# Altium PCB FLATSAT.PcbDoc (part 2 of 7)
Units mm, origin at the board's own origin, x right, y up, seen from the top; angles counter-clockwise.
Board outline 430 x 350 mm, 5 copper layers (Top Layer, Internal Plane 1, Internal Plane 2, DELETEME, Bottom Layer); 808 components, 852 nets, 6407 pads, 939 vias.
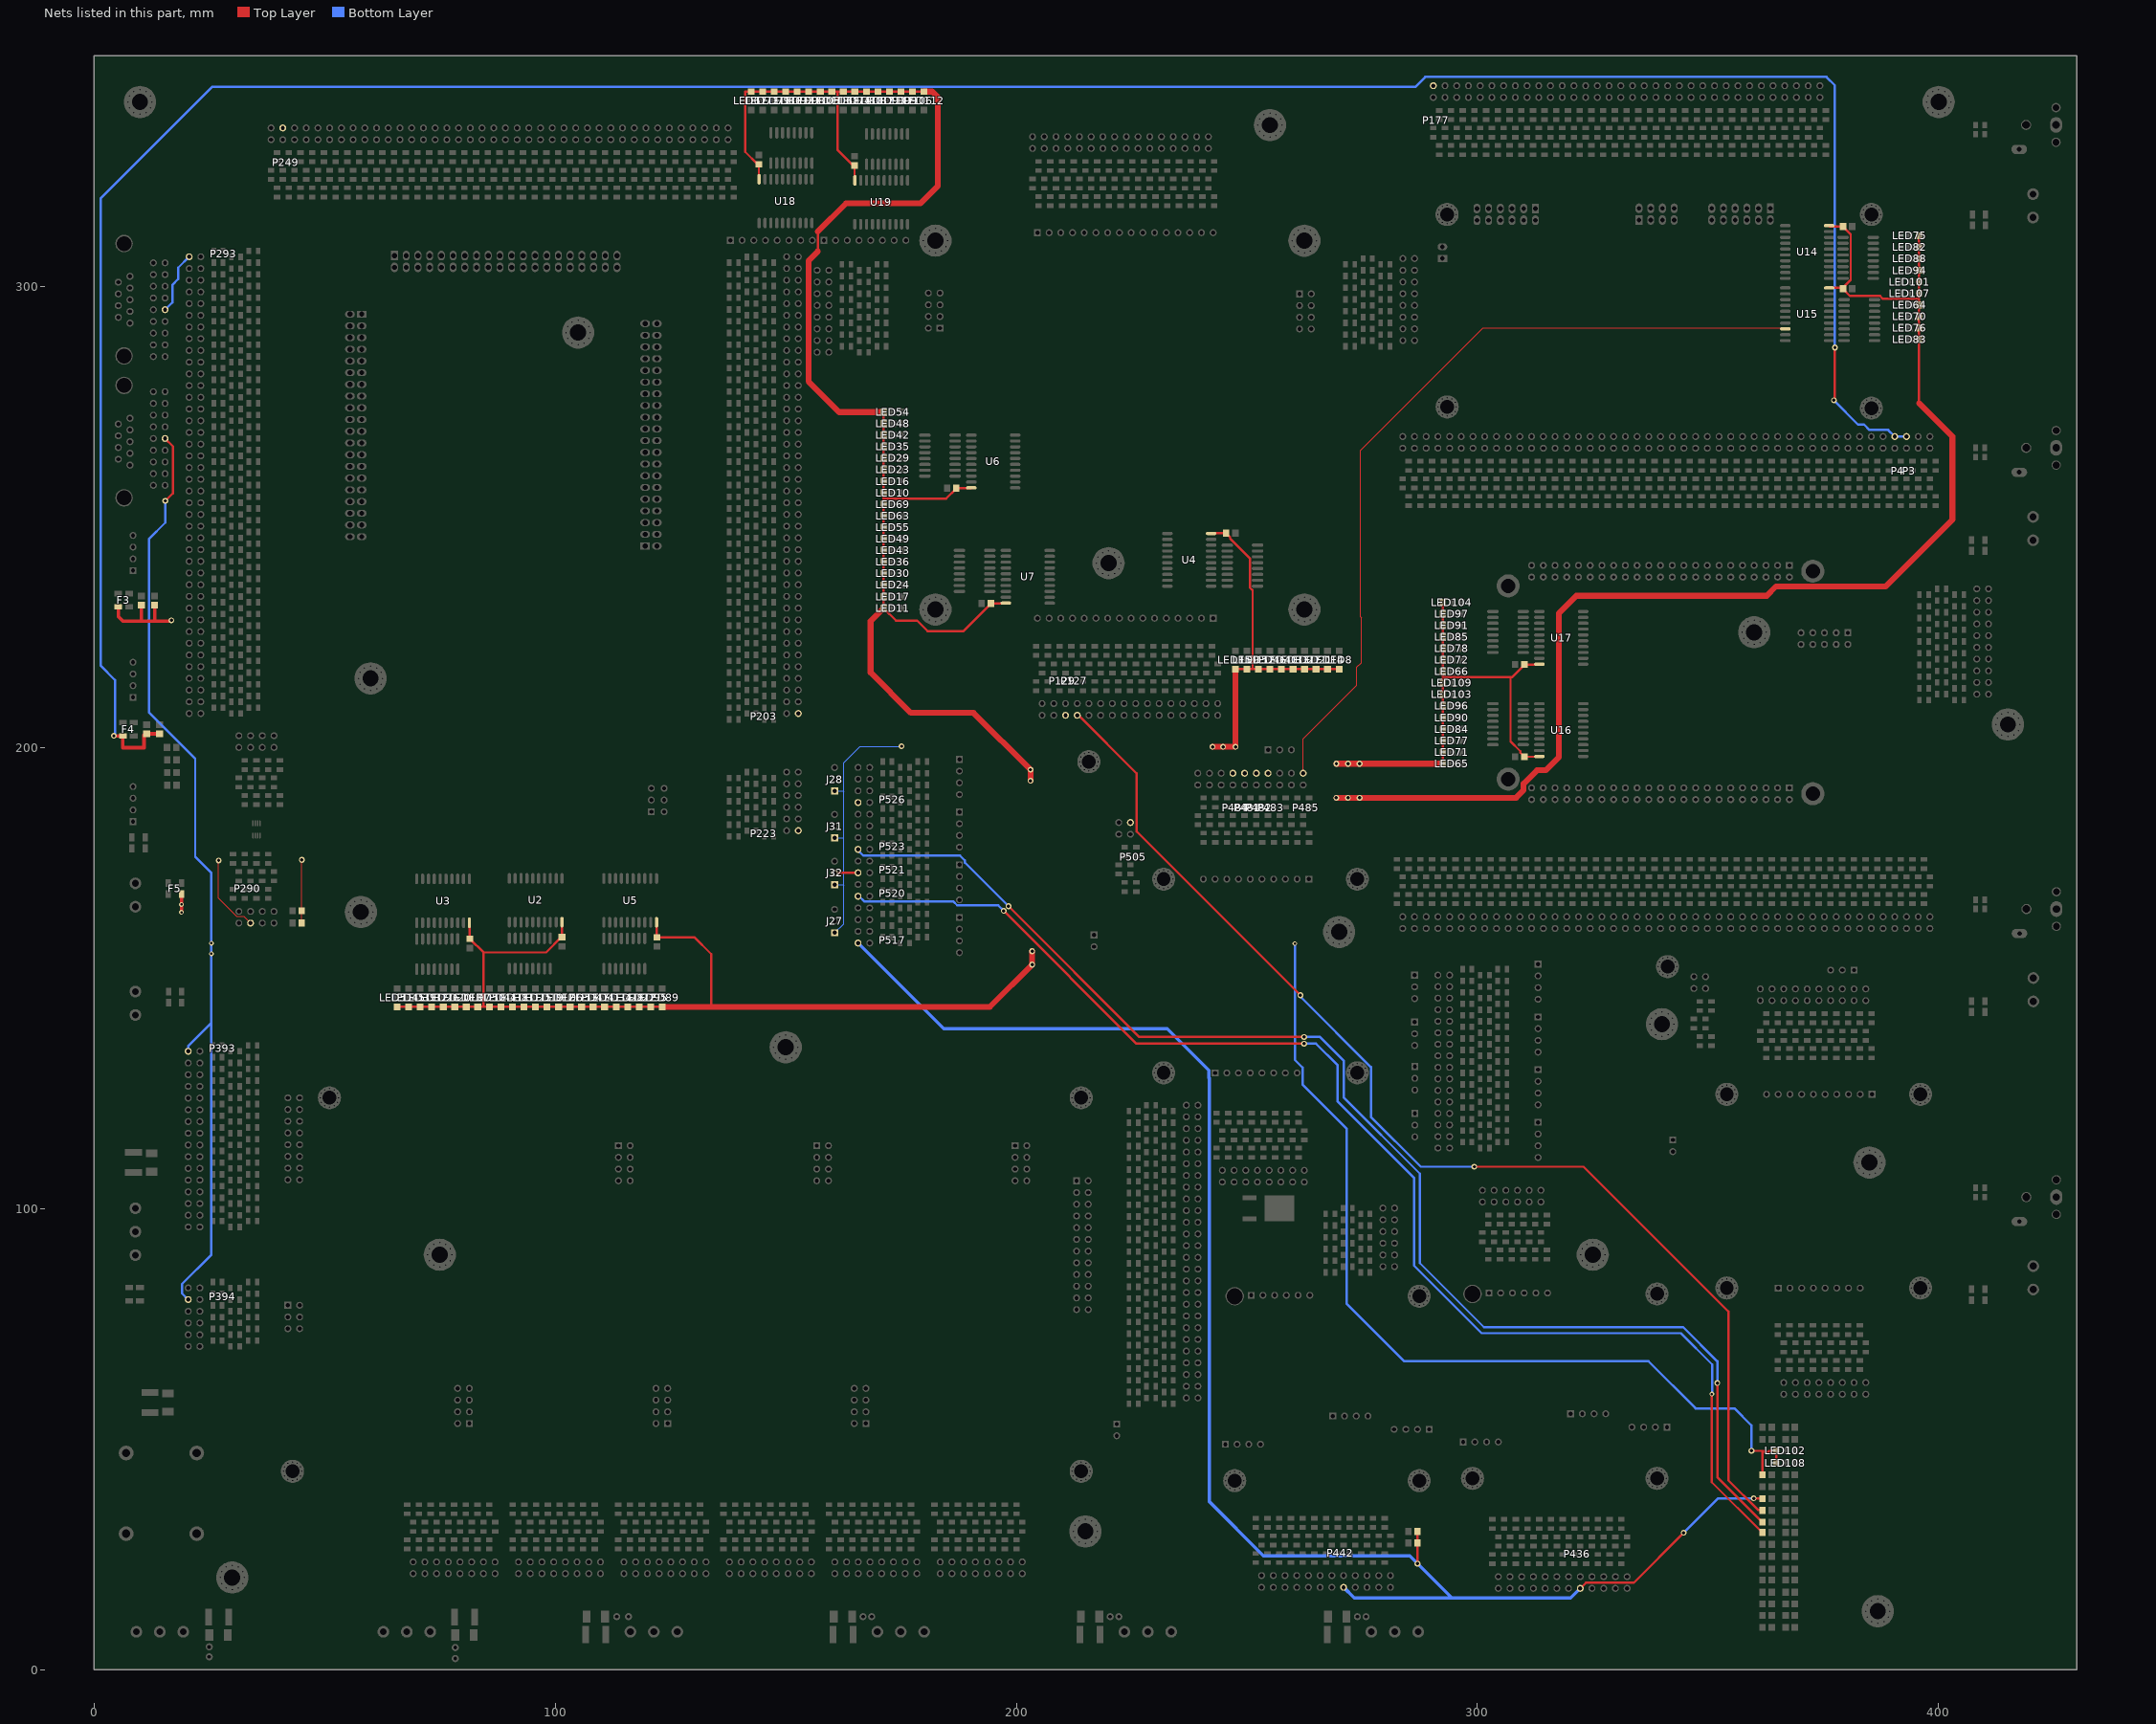
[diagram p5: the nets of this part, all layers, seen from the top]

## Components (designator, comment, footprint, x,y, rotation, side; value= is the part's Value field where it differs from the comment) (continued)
P532 "Jumper_Filter" Jumper_filter#1 291.418,123.14 r0 top
P533 "Jumper_Filter" Jumper_filter#1 291.418,128.14 r0 top
P534 "Jumper_Filter" Jumper_filter#1 291.418,130.64 r0 top
P535 "Jumper_Filter" Jumper_filter#1 291.418,133.14 r0 top
P536 "Jumper_Filter" Jumper_filter#1 291.418,138.14 r0 top
P537 "Jumper_Filter" Jumper_filter#1 291.418,140.64 r0 top
P538 "Jumper_Filter" Jumper_filter#1 291.418,143.14 r0 top
P539 "Jumper_Filter" Jumper_filter#1 291.418,148.14 r0 top
P540 "Jumper_Filter" Jumper_filter#1 291.418,150.64 r0 top
R1 "1206 Resistor" 6-0805_M 14.224,203.962 r90 top
R2 "1206 Resistor" 6-0805_M 11.43,203.962 r90 top
R3 "1206 Resistor" 6-0805_M 13.183,231.877 r90 top
R4 "1206 Resistor" 6-0805_M 10.312,231.877 r90 top
R5 "1206 Resistor" 6-0805_M 286,27.5 r180 top
R6 "1206 Resistor" 6-0805_M 286,30 r180 top
R7 "1206 Resistor" 6-0805_M 44.069,164.592 r180 top
R8 "1206 Resistor" 6-0805_M 44.069,161.925 r180 top
R9 "1206 Resistor" 6-0805_M 16.904,191.829 r0 top
R10 "1206 Resistor" 6-0805_M 16.904,194.579 r0 top
R11 "1206 Resistor" 6-0805_M 16.904,197.329 r0 top
R12 "Res2" 6-0805_M 362.803,52.585 r180 top
R13 "Res2" 6-0805_M 362.803,49.965 r180 top
R14 "Res2" 6-0805_M 362.803,42.265 r180 top
R15 "Res2" 6-0805_M 362.803,39.685 r180 top
R16 "Res2" 6-0805_M 362.803,37.105 r180 top
R17 "Res2" 6-0805_M 362.803,34.525 r180 top
R18 "Res2" 6-0805_M 362.803,32.025 r180 top
R19 "Res2" 6-0805_M 362.803,29.765 r180 top
R20 "Res2" 6-0805_M 362.803,27.185 r180 top
R21 "Res2" 6-0805_M 362.803,24.605 r180 top
R22 "Res2" 6-0805_M 362.803,21.865 r180 top
R23 "Res2" 6-0805_M 362.803,19.445 r180 top
R24 "Res2" 6-0805_M 362.803,11.785 r180 top
R25 "Res2" 6-0805_M 362.803,16.825 r180 top
R26 "Res2" 6-0805_M 362.803,9.165 r180 top
R27 "Res2" 6-0805_M 362.803,14.245 r180 top
SW1 "3V3" LVSwitcher 277.956,125.459 r90 top locked
SW2 "5V0" LVSwitcher 400.059,78.786 r90 top locked
TRX1 "TRX_REGULATOR" TRX_REGULATOR 342.218,84.66 r180 top locked
TRX2 "TRX_REGULATOR" TRX_REGULATOR 290.656,84.168 r180 top locked
U1 "PCA9306" TSSOP50P310X90-8N 35.249,182.24 r90 top
U2 "MC74VHC541DW" 751D-04_M 95.79,166.875 r270 top
U3 "MC74VHC541DW" 751D-04_M 75.715,166.75 r270 top
U4 "MC74VHC541DW" 751D-04_M 237.5,240.715 r0 top
U5 "MC74VHC541DW" 751D-04_M 116.288,166.85 r270 top
U6 "MC74VHC541DW" 751D-04_M 195,262.035 r180 top
U7 "MC74VHC541DW" 751D-04_M 202.5,237.035 r180 top
U8 "SOMC1603" SOMC1603 89.059,160.366 r270 top
U9 "SOMC1603" SOMC1603 68.984,160.241 r270 top
U10 "SOMC1603" SOMC1603 244.009,233.984 r0 top
U11 "SOMC1603" SOMC1603 109.557,160.341 r270 top
U12 "SOMC1603" SOMC1603 188.491,268.766 r180 top
U13 "SOMC1603" SOMC1603 195.991,243.766 r180 top
U14 "MC74VHC541DW" 751D-04_M 371.5,307.465 r0 top
U15 "MC74VHC541DW" 751D-04_M 371.5,293.965 r0 top
U16 "MC74VHC541DW" 751D-04_M 318.171,203.785 r180 top
U17 "MC74VHC541DW" 751D-04_M 318.171,223.785 r180 top
U18 "MC74VHC541DW" 751D-04_M 149.965,318.5 r90 top
U19 "MC74VHC541DW" 751D-04_M 170.715,318.25 r90 top
U20 "SOMC1603" SOMC1603 377.509,300.734 r0 top
U21 "SOMC1603" SOMC1603 377.759,287.234 r0 top
U22 "SOMC1603" SOMC1603 311.662,210.516 r180 top
U23 "SOMC1603" SOMC1603 311.662,230.516 r180 top
U24 "SOMC1603" SOMC1603 156.696,325.009 r90 top
U25 "SOMC1603" SOMC1603 177.446,324.759 r90 top

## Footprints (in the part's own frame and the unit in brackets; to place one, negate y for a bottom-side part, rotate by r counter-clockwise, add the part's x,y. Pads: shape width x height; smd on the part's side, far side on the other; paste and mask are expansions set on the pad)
4MM_BANANA [mm] "DELTRON 571-0x00"
  round 3.2 hole 1.8: 1(0,0) 1(15.3,0)
  silkscreen extent -2.5,-5 20.25,5
6-0805_M [mm] "Chip Resistor, Body 2.0x1.2mm, IPC Low Density"
  rect 1.4x1.5 smd: 1(-1,0) 2(1,0)
  silkscreen extent 0,-0.65 0,0.65, body extent -1.07,-0.7 1.07,0.7, height 0.7
751D-04_M [mm] "SOIC, 20-Leads, Body 12.8x7.5mm, Pitch 1.27mm, IPC Low Density"
  oval 2.3x0.7 smd: 1(-4.75,5.715) 2(-4.75,4.445) 3(-4.75,3.175) 4(-4.75,1.905) 5(-4.75,0.635) 6(-4.75,-0.635) 7(-4.75,-1.905) 8(-4.75,-3.175) 9(-4.75,-4.445) 10(-4.75,-5.715) 11(4.75,-5.715) 12(4.75,-4.445) 13(4.75,-3.175) 14(4.75,-1.905) 15(4.75,-0.635) 16(4.75,0.635) 17(4.75,1.905) 18(4.75,3.175) 19(4.75,4.445) 20(4.75,5.715)
  silkscreen extent -4.87,-6.5 3.2,6.74, body extent -3.8,-6.5 3.8,6.5, height 2.65
BCR [mm]
  round 1 hole 0.3: 0(2.5,85.5) 0(2.5,4.5) 0(2.768,84.5) 0(2.768,86.5) 0(2.768,5.5) 0(2.768,3.5) 0(3.5,87.232) 0(3.5,83.768) 0(3.5,6.232) 0(3.5,2.768) 0(4.5,87.5) 0(4.5,83.5) 0(4.5,6.5) 0(4.5,2.5) 0(5.5,87.232) 0(5.5,83.768) 0(5.5,6.232) 0(5.5,2.768) 0(6.232,86.5) 0(6.232,84.5) 0(6.232,3.5) 0(6.232,5.5) 0(6.5,85.5) 0(6.5,4.5) 0(165.5,4.5) 0(165.768,3.5) 0(165.768,5.5) 0(166.5,2.768) 0(166.5,6.232) 0(167.5,2.5) 0(167.5,6.5) 0(168.5,2.768) 0(168.5,6.232) 0(169.232,3.5) 0(169.232,5.5) 0(169.5,4.5) 0(173.5,85.5) 0(173.768,84.5) 0(173.768,86.5) 0(174.5,83.768) 0(174.5,87.232) 0(175.5,83.5) 0(175.5,87.5) 0(176.5,83.768) 0(176.5,87.232) 0(177.232,84.5) 0(177.232,86.5) 0(177.5,85.5)
  round 5 hole 3: 0(4.5,85.5) 0(4.5,4.5) 0(167.5,4.5) 0(175.5,85.5)
  round 1.5 hole 0.9: 1(173.96,49.5) 1(176.5,4.5) 2(173.96,4.5) 3(173.96,54.58) 3(173.96,7.04) 3(173.96,9.58) 3(173.96,12.12) 3(173.96,14.66) 3(173.96,17.2) 3(173.96,19.74) 3(173.96,22.28) 4(176.5,54.58) 4(176.5,22.28) 5(176.5,14.66) 6(176.5,12.12) 7(176.5,9.58) 8(176.5,7.04) 9(176.5,17.2) 10(176.5,19.74) 11(5.5,50.44) 11(5.5,45.36) 11(5.5,47.9) 11(5.5,40.28) 11(5.5,42.82) 11(5.5,35.2) 11(5.5,37.74) 13(5.5,32.66) 13(5.5,27.58) 13(5.5,30.12) 13(5.5,25.04) 14(-3.2,77.79) 14(2.96,50.44) 14(2.96,47.9) 14(2.96,42.82) 14(2.96,45.36) 14(2.96,40.28) 14(2.96,37.74) 14(2.96,35.2) 14(2.96,32.66) 14(2.96,30.12) 14(2.96,27.58) 14(2.96,22.5) 14(2.96,25.04) 15(61.834,17.407) 15(61.834,19.947) 15(61.834,22.487) 16(59.294,17.407) 16(59.294,19.947) 16(59.294,22.487) 17(59.294,14.867) 18(104.834,17.407) 18(104.834,19.947) 18(104.834,22.487) 19(102.294,17.407) 19(102.294,19.947) 19(102.294,22.487) 20(102.294,14.867) 21(18.834,17.407) 21(18.834,19.947) 21(18.834,22.487) 22(16.294,17.407) 22(16.294,19.947) 22(16.294,22.487) 23(16.294,14.867) 24(94.166,67.513) 24(94.166,70.053) 24(94.166,72.593) 25(96.706,67.513) 25(96.706,70.053) 25(96.706,72.593) 26(96.706,75.133) 27(51.166,72.593) 27(51.166,67.513) 27(51.166,70.053) 28(53.706,67.513) 28(53.706,70.053) 28(53.706,72.593) 29(53.706,75.133) 30(137.166,67.513) 30(137.166,70.053) 30(137.166,72.593) 31(139.706,67.513) 31(139.706,70.053) 31(139.706,72.593) 32(139.706,75.133) 34(176.5,52.04) 35(173.96,52.04)
  rect 1.5x1.5 hole 0.9: 12(-3.2,75.25) 13(5.5,22.5) 15(61.834,14.867) 18(104.834,14.867) 21(18.834,14.867) 24(94.166,75.133) 27(51.166,75.133) 30(137.166,75.133) 33(176.5,49.5)
  silkscreen extent -4.47,0 180,90
Beaglebone [mil]
  rect 60x60 hole 31.5 mask+2.76: A01(2625,-75) B01(2625,-1975) P01(3125,-650)
  round 60 hole 31.5 mask+2.76: A02(2625,-175) A03(2525,-75) A04(2525,-175) A05(2425,-75) A06(2425,-175) A07(2325,-75) A08(2325,-175) A09(2225,-75) A10(2225,-175) A11(2125,-75) A12(2125,-175) A13(2025,-75) A14(2025,-175) A15(1925,-75) A16(1925,-175) A17(1825,-75) A18(1825,-175) A19(1725,-75) A20(1725,-175) A21(1625,-75) A22(1625,-175) A23(1525,-75) A24(1525,-175) A25(1425,-75) A26(1425,-175) A27(1325,-75) A28(1325,-175) A29(1225,-75) A30(1225,-175) A31(1125,-75) A32(1125,-175) A33(1025,-75) A34(1025,-175) A35(925,-75) A36(925,-175) A37(825,-75) A38(825,-175) A39(725,-75) A40(725,-175) A41(625,-75) A42(625,-175) A43(525,-75) A44(525,-175) A45(425,-75) A46(425,-175) B02(2625,-2075) B03(2525,-1975) B04(2525,-2075) B05(2425,-1975) B06(2425,-2075) B07(2325,-1975) B08(2325,-2075) B09(2225,-1975) B10(2225,-2075) B11(2125,-1975) B12(2125,-2075) B13(2025,-1975) B14(2025,-2075) B15(1925,-1975) B16(1925,-2075) B17(1825,-1975) B18(1825,-2075) B19(1725,-1975) B20(1725,-2075) B21(1625,-1975) B22(1625,-2075) B23(1525,-1975) B24(1525,-2075) B25(1425,-1975) B26(1425,-2075) B27(1325,-1975) B28(1325,-2075) B29(1225,-1975) B30(1225,-2075) B31(1125,-1975) B32(1125,-2075) B33(1025,-1975) B34(1025,-2075) B35(925,-1975) B36(925,-2075) B37(825,-1975) B38(825,-2075) B39(725,-1975) B40(725,-2075) B41(625,-1975) B42(625,-2075) B43(525,-1975) B44(525,-2075) B45(425,-1975) B46(425,-2075) P02(3125,-750) P03(3025,-650) P04(3025,-750) P05(2925,-650) P06(2925,-750) P07(2825,-650) P08(2825,-750) P09(2725,-650) P10(2725,-750)
  round 196.85 hole 122.05 mask+2.76: M1(225,-250) M2(225,-1900) M3(2825,-125) M4(2825,-2025)
  silkscreen extent 0,-2150 3400,0
"BIDIRECTIONAL LED" [mm]
  rect 1.4x1.5 smd: 1(-1,0) 2(1,0) 3(3,0)
  silkscreen extent -2.02,1.15 -2,1.15
Communications [mm] "Communications"
  round 1.5 hole 0.9: AFSK1_M0(32.192,86.733) AFSK1_M1(29.652,86.733) AFSK1_RXD(34.732,86.733) AFSK2_M0(62.672,86.733) AFSK2_M1(60.132,86.733) AFSK2_RXD(65.212,86.733) AFSK2_TXD(57.592,86.733) DTMF1_Q1(52.512,3.113) DTMF1_Q2(55.052,3.113) DTMF1_Q3(57.592,3.113) DTMF1_Q4(60.132,3.113) DTMF1_ST(62.672,3.113) DTMF2_ES(49.972,3.113) DTMF2_Q1(37.272,3.113) DTMF2_Q2(39.812,3.113) DTMF2_Q3(42.352,3.113) DTMF2_Q4(44.892,3.113) DTMF2_ST(47.432,3.113) GMSK_RX1(83.952,70.923) GMSK_RX2(83.952,65.843) GMSK_TX2(83.952,68.383) GND(3.462,66.013) GND(3.462,68.553) GND(3.462,71.093) GND(3.462,73.633) GND(27.112,3.113) GND(29.652,3.113) GND(86.492,65.843) GND(86.492,68.383) GND(86.492,70.923) GND(86.492,73.463) RX1(6.002,68.553) S0(55.052,86.733) S1(52.512,86.733) S2(49.972,86.733) S3(47.432,86.733) S4(44.892,86.733) S5(42.352,86.733) S6(39.812,86.733) S7(37.272,86.733) TX1(6.002,73.633) TX2(6.002,71.093) VCC(32.192,3.113) VCC(34.732,3.113)
  rect 1.5x1.5 hole 0.9: AFSK1_TXD(27.112,86.733) DTMF1_ES(65.212,3.113) GMSK_TX1(83.952,73.463) RX2(6.002,66.013)
  round 1 hole 0.3: ""(2.377,5.013) ""(2.377,85.013) ""(2.729,3.701) ""(2.729,6.325) ""(2.729,83.701) ""(2.729,86.325) ""(3.69,7.286) ""(3.69,87.286) ""(3.69,2.74) ""(3.69,82.74) ""(5.002,2.388) ""(5.002,7.638) ""(5.002,82.388) ""(5.002,87.638) ""(6.314,2.74) ""(6.314,7.286) ""(6.314,82.74) ""(6.314,87.286) ""(7.275,3.701) ""(7.275,83.701) ""(7.275,6.325) ""(7.275,86.325) ""(7.627,5.013) ""(7.627,85.013) ""(82.375,85) ""(82.377,5.013) ""(82.727,83.688) ""(82.727,86.312) ""(82.729,3.701) ""(82.729,6.325) ""(83.688,87.273) ""(83.688,82.727) ""(83.69,7.286) ""(83.69,2.74) ""(85,82.375) ""(85,87.625) ""(85.002,2.388) ""(85.002,7.638) ""(86.312,82.727) ""(86.312,87.273) ""(86.314,2.74) ""(86.314,7.286) ""(87.273,83.688) ""(87.273,86.312) ""(87.275,3.701) ""(87.275,6.325) ""(87.625,85) ""(87.627,5.013)
  round 7 hole 3.5: ""(5.002,5.013) ""(5.002,85.013) ""(85,85) ""(85.002,5.013)
  silkscreen extent 0,0.01 90,90.01
CSC [mm] "Critical Systems Computer"
  rect 1.5x2.1 hole 1.1: C1_1(68.259,68.588) C3_1(17.967,7.12)
  oval 1.5x2.1 hole 1.1: C1_2(68.259,71.128) C1_3(65.719,68.588) C1_4(65.719,71.128) C1_5(63.179,68.588) C1_6(63.179,71.128) C1_7(60.639,68.588) C1_8(60.639,71.128) C1_9(58.099,68.588) C1_10(58.099,71.128) C1_11(55.559,68.588) C1_12(55.559,71.128) C1_13(53.019,68.588) C1_14(53.019,71.128) C1_15(50.479,68.588) C1_16(50.479,71.128) C1_17(47.939,68.588) C1_18(47.939,71.128) C1_19(45.399,68.588) C1_20(45.399,71.128) C1_21(42.859,68.588) C1_22(42.859,71.128) C1_23(40.319,68.588) C1_24(40.319,71.128) C1_25(37.779,68.588) C1_26(37.779,71.128) C1_27(35.239,68.588) C1_28(35.239,71.128) C1_29(32.699,68.588) C1_30(32.699,71.128) C1_31(30.159,68.588) C1_32(30.159,71.128) C1_33(27.619,68.588) C1_34(27.619,71.128) C1_35(25.079,68.588) C1_36(25.079,71.128) C1_37(22.539,68.588) C1_38(22.539,71.128) C1_39(19.999,68.588) C1_40(19.999,71.128) C3_2(17.967,4.58) C3_3(20.507,7.12) C3_4(20.507,4.58) C3_5(23.047,7.12) C3_6(23.047,4.58) C3_7(25.587,7.12) C3_8(25.587,4.58) C3_9(28.127,7.12) C3_10(28.127,4.58) C3_11(30.667,7.12) C3_12(30.667,4.58) C3_13(33.207,7.12) C3_14(33.207,4.58) C3_15(35.747,7.12) C3_16(35.747,4.58) C3_17(38.287,7.12) C3_18(38.287,4.58) C3_19(40.827,7.12) C3_20(40.827,4.58) C3_21(43.367,7.12) C3_22(43.367,4.58) C3_23(45.907,7.12) C3_24(45.907,4.58) C3_25(48.447,7.12) C3_26(48.447,4.58) C3_27(50.987,7.12) C3_28(50.987,4.58) C3_29(53.527,7.12) C3_30(53.527,4.58) C3_31(56.067,7.12) C3_32(56.067,4.58) C3_33(58.607,7.12) C3_34(58.607,4.58) C3_35(61.147,7.12) C3_36(61.147,4.58) C3_37(63.687,7.12) C3_38(63.687,4.58) C3_39(66.227,7.12) C3_40(66.227,4.58)
  rect 2.1x1.5 hole 1.1: C2_1(5.267,14.232)
  oval 2.1x1.5 hole 1.1: C2_2(7.807,14.232) C2_3(5.267,16.772) C2_4(7.807,16.772) C2_5(5.267,19.312) C2_6(7.807,19.312) C2_7(5.267,21.852) C2_8(7.807,21.852) C2_9(5.267,24.392) C2_10(7.807,24.392) C2_11(5.267,26.932) C2_12(7.807,26.932) C2_13(5.267,29.472) C2_14(7.807,29.472) C2_15(5.267,32.012) C2_16(7.807,32.012) C2_17(5.267,34.552) C2_18(7.807,34.552) C2_19(5.267,37.092) C2_20(7.807,37.092) C2_21(5.267,39.632) C2_22(7.807,39.632) C2_23(5.267,42.172) C2_24(7.807,42.172) C2_25(5.267,44.712) C2_26(7.807,44.712) C2_27(5.267,47.252) C2_28(7.807,47.252) C2_29(5.267,49.792) C2_30(7.807,49.792) C2_31(5.267,52.332) C2_32(7.807,52.332) C2_33(5.267,54.872) C2_34(7.807,54.872) C2_35(5.267,57.412) C2_36(7.807,57.412) C2_37(5.267,59.952) C2_38(7.807,59.952) C2_39(5.267,62.492) C2_40(7.807,62.492)
  rect 1.5x1.5 hole 0.9: ISP1(125.877,69.923)
  round 1.5 hole 0.9: ISP2(123.337,69.923) ISP3(120.797,69.923) ISP4(125.877,72.713) ISP5(123.337,72.713) ISP6(120.797,72.713)
  round 1 hole 0.3: ""(145,6.95) ""(145.352,5.638) ""(145.352,8.262) ""(146.313,9.223) ""(146.313,4.677) ""(147.625,4.325) ""(147.625,9.575) ""(148.937,4.677) ""(148.937,9.223) ""(149.898,5.638) ""(149.898,8.262) ""(150.25,6.95)
  round 7 hole 3.5: ""(147.625,6.95)
  silkscreen extent 0,0 160,75
"D9 - temp" [mil] "GLENAIR MICRO-D9"
  round 60 hole 35.43: 1(-150,100) 2(-50,100) 3(0,0) 4(50,100) 5(150,100) 6(-200,0) 7(-100,0) 8(100,0) 9(200,0)
  round 149.61 hole 125.98: 10(-479.85,50.47) 11(479.85,50.47)
  silkscreen extent -591,-98 591,453
Filter [mm]
  rect 1x1.4 smd: 1(-1,2) 2(1,0) 2(1,2) 3(-1,0)
  silkscreen extent 0,1.35 0,2.65, body extent -1.1,-0.65 1.1,2.65, height 0.5
FILTERPWR [mm]
  rect 1.15x1.7 smd: 1(-1.425,2.35) 2(1.425,0) 2(1.425,2.35) 3(-1.425,0)
  silkscreen extent 0,1.7 0,3, body extent -1.63,-0.82 1.62,3.17, height 0.7
FILTERSOLA [mm]
  rect 1.45x3.65 smd: 1(-2.175,3.9) 2(2.175,3.9)
  rect 1.7x2.5 smd: 2(2,0) 3(-2,0)
  silkscreen extent 0,2.55 0,5.2, body extent -2.45,2.1 2.45,5.7, height 2
GMSK [mm] "Foot print of GMSK for the flatsat board"
  rect 1.5x2.1 hole 1: 1A(22.15,47.03) 1B(73.05,47.08) 1C(44.59,44.54)
  oval 1.5x2.1 hole 1: 2A(22.15,44.49) 2B(73.05,44.54) 3A(19.61,47.03) 3B(70.51,47.08) 3C(47.13,44.54) 4A(19.61,44.49) 4B(70.51,44.54) 5A(17.07,47.03) 5B(67.97,47.08) 5C(49.67,44.54) 6A(17.07,44.49) 6B(67.97,44.54) 7A(14.53,47.03) 7B(65.43,47.08) 7C(52.21,44.54) 8A(14.53,44.49) 8B(65.43,44.54) 8C(9.45,47.03) 8C(44.59,47.08) 8C(47.13,47.08) 8C(49.67,47.08) 8C(52.21,47.08) 8C(60.35,47.08) 9A(11.99,47.03) 9B(62.89,47.08) 10A(11.99,44.49) 10B(62.89,44.54) 12A(9.45,44.49) 12B(60.35,44.54)
  oval 2.1x1.5 hole 1: 2C(1.97,38.74)
  rect 2.1x1.5 hole 1: 8C(1.97,36.2)
  round 1 hole 0.3: ""(0.97,45.74) ""(1,4) ""(1.238,44.74) ""(1.238,46.74) ""(1.268,3) ""(1.268,5) ""(1.97,44.008) ""(1.97,47.472) ""(2,2.268) ""(2,5.732) ""(2.97,43.74) ""(2.97,47.74) ""(3,2) ""(3,6) ""(3.97,44.008) ""(3.97,47.472) ""(4,2.268) ""(4,5.732) ""(4.702,44.74) ""(4.702,46.74) ""(4.732,3) ""(4.732,5) ""(4.97,45.74) ""(5,4) ""(92.97,3.74) ""(92.97,45.74) ""(93.238,2.74) ""(93.238,4.74) ""(93.238,44.74) ""(93.238,46.74) ""(93.97,2.008) ""(93.97,5.472) ""(93.97,44.008) ""(93.97,47.472) ""(94.97,1.74) ""(94.97,5.74) ""(94.97,43.74) ""(94.97,47.74) ""(95.97,2.008) ""(95.97,5.472) ""(95.97,44.008) ""(95.97,47.472) ""(96.702,2.74) ""(96.702,4.74) ""(96.702,44.74) ""(96.702,46.74) ""(96.97,3.74) ""(96.97,45.74)
  round 5 hole 3: ""(2.97,45.74) ""(3,4) ""(94.97,3.74) ""(94.97,45.74)
  silkscreen extent -0.03,0.74 97.97,48.94, body extent 0.8,35.03 74.23,48.26, height 7.01
HDR1X3 [mm] "Connector; Header; 3 Position"
  rect 1.5x1.5 hole 0.9: 1(0,0)
  round 1.5 hole 0.9: 2(2.54,0) 3(5.08,0)
  silkscreen extent -1.27,-1.27 6.35,1.27
HDR1X4 [mm] "Connector; Header; 4 Position"
  rect 1.5x1.5 hole 0.9: 1(0,0)
  round 1.5 hole 0.9: 2(2.54,0) 3(5.08,0) 4(7.62,0)
  silkscreen extent -1.27,-1.27 8.89,1.27
HDR1X8 [mm] "Connector; Header; 8 Position"
  rect 1.5x1.5 hole 0.9: 1(0,0)
  round 1.5 hole 0.9: 2(2.54,0) 3(5.08,0) 4(7.62,0) 5(10.16,0) 6(12.7,0) 7(15.24,0) 8(17.78,0)
  silkscreen extent -1.27,-1.27 19.05,1.27
HOLE3.5 [mm]
  round 1 hole 0.3: 1(-2.625,0) 1(-2.273,-1.312) 1(-2.273,1.312) 1(-1.312,2.273) 1(-1.312,-2.273) 1(0,-2.625) 1(0,2.625) 1(1.312,-2.273) 1(1.312,2.273) 1(2.273,-1.312) 1(2.273,1.312) 1(2.625,0)
  round 7 hole 3.5: 1(0,0)
Jumper [mm] "Connector; Header; 2 Position"
  round 1.5 hole 0.9: 1(0,0) 2(2.54,0)
Jumper_filter#1 [mm] "Connector; Header; 2 Position"
  round 1.5 hole 0.9: 1(0,0) 2(2.54,0)
  rect 1x1.4 smd: 2(5.35,1.27) 2(7.35,1.27) 2(9.16,0) 2(12.97,1.27) 2(14.97,1.27) 3(11.16,0)
  Top Layer lines w0.152: 14.986,1.27 14.97,1.27 12.97,1.27 12.954,1.27 9.144,1.27 7.366,1.27 ; 5.334,1.27 5.35,1.27 7.35,1.27 7.366,1.27 ; 7.366,1.016 7.366,1.27 ; 7.366,1.016 7.366,1.27 ; 7.366,1.016 7.366,1.27 ; 7.366,1.016 7.366,1.27 ; 7.366,1.016 7.366,1.27 ; 7.366,1.016 7.366,1.27 ; 7.366,1.016 7.366,1.27 ; 7.366,1.016 7.366,1.27
  Top Layer lines w0.254: 16.51,0 11.43,0 ; 2.54,0 3.81,1.27 5.08,1.27 ; 12.954,1.27 9.144,1.27 ; 7.366,1.27 9.144,1.27 ; 9.144,0 9.144,1.27 ; 9.144,0 9.144,1.27 ; 9.144,0 9.144,1.27 ; 9.144,0 9.144,1.27 ; 9.144,0 9.144,1.27 ; 9.144,0 9.144,1.27 ; 9.144,0 9.144,1.27 ; 9.144,0 9.144,1.27
  silkscreen extent 10.16,-0.65 13.97,1.92, body extent 5.25,-0.65 15.07,1.92, height 0.5
Jumper_filter#2 [mm] "Connector; Header; 2 Position"
  round 1.5 hole 0.9: 1(0,0) 2(2.54,0)
  rect 1x1.4 smd: 2(5.35,1.27) 2(7.35,1.27) 2(9.16,0) 2(12.97,1.27) 2(14.97,1.27) 3(11.16,0)
  Top Layer lines w0.152: 14.986,1.27 14.97,1.27 12.97,1.27 12.954,1.27 9.144,1.27 7.366,1.27 ; 5.334,1.27 5.35,1.27 7.35,1.27 7.366,1.27 ; 7.366,1.016 7.366,1.27 ; 7.366,1.016 7.366,1.27 ; 7.366,1.016 7.366,1.27 ; 7.366,1.016 7.366,1.27 ; 7.366,1.016 7.366,1.27 ; 7.366,1.016 7.366,1.27 ; 7.366,1.016 7.366,1.27 ; 7.366,1.016 7.366,1.27
  Top Layer lines w0.254: 16.51,0 11.43,0 ; 2.54,0 3.81,1.27 4.981,1.27 5.08,1.27 ; 12.954,1.27 9.144,1.27 ; 7.366,1.27 9.144,1.27 ; 9.144,0 9.144,1.27 ; 9.144,0 9.144,1.27 ; 9.144,0 9.144,1.27 ; 9.144,0 9.144,1.27 ; 9.144,0 9.144,1.27 ; 9.144,0 9.144,1.27 ; 9.144,0 9.144,1.27 ; 9.144,0 9.144,1.27
  silkscreen extent 10.16,-0.65 13.97,1.92, body extent 5.25,-0.65 15.07,1.92, height 0.5
Jumper_filter#3 [mm] "Connector; Header; 2 Position"
  round 1.5 hole 0.9: 1(0,0) 2(2.54,0)
  rect 1x1.4 smd: 2(5.35,1.27) 2(7.35,1.27) 2(9.16,0) 2(12.97,1.27) 2(14.97,1.27) 3(11.16,0)
  Top Layer lines w0.152: 14.986,1.27 14.97,1.27 12.97,1.27 12.954,1.27 9.144,1.27 7.366,1.27 ; 5.334,1.27 5.35,1.27 7.35,1.27 7.366,1.27 ; 7.366,1.016 7.366,1.27 ; 7.366,1.016 7.366,1.27 ; 7.366,1.016 7.366,1.27 ; 7.366,1.016 7.366,1.27 ; 7.366,1.016 7.366,1.27 ; 7.366,1.016 7.366,1.27 ; 7.366,1.016 7.366,1.27 ; 7.366,1.016 7.366,1.27
  Top Layer lines w0.254: 16.51,0 11.43,0 ; 2.54,0 3.81,1.27 4.12,1.27 4.225,1.27 5.08,1.27 ; 12.954,1.27 9.144,1.27 ; 7.366,1.27 9.144,1.27 ; 9.144,0 9.144,1.27 ; 9.144,0 9.144,1.27 ; 9.144,0 9.144,1.27 ; 9.144,0 9.144,1.27 ; 9.144,0 9.144,1.27 ; 9.144,0 9.144,1.27 ; 9.144,0 9.144,1.27 ; 9.144,0 9.144,1.27
  silkscreen extent 10.16,-0.65 13.97,1.92, body extent 5.25,-0.65 15.07,1.92, height 0.5
Jumper_filter#4 [mm] "Connector; Header; 2 Position"
  round 1.5 hole 0.9: 1(0,0) 2(2.54,0)
  rect 1x1.4 smd: 2(5.35,1.27) 2(7.35,1.27) 2(9.16,0) 2(12.97,1.27) 2(14.97,1.27) 3(11.16,0)
  Top Layer lines w0.152: 5.334,1.27 5.35,1.27 7.35,1.27 7.366,1.27 ; 14.986,1.27 14.97,1.27 12.97,1.27 ; 7.366,1.27 7.366,1.016 ; 7.366,1.27 7.366,1.016 ; 7.366,1.27 7.366,1.016 ; 7.366,1.27 7.366,1.016 ; 7.366,1.27 7.366,1.016 ; 7.366,1.27 7.366,1.016 ; 7.366,1.27 7.366,1.016 ; 7.366,1.27 7.366,1.016 ; 7.366,1.27 9.144,1.27 ; 9.144,1.27 12.954,1.27 ; 9.144,1.27 12.954,1.27 ; 12.954,1.27 12.97,1.27 ; 12.954,1.27 12.97,1.27
  Top Layer lines w0.254: 5.08,1.27 3.81,1.27 2.54,0 ; 7.366,1.27 9.144,1.27 ; 12.954,1.27 9.144,1.27 ; 11.43,0 16.51,0 ; 9.144,1.27 9.144,0 ; 9.144,1.27 9.144,0 ; 9.144,1.27 9.144,0 ; 9.144,1.27 9.144,0 ; 9.144,1.27 9.144,0 ; 9.144,1.27 9.144,0 ; 9.144,1.27 9.144,0 ; 9.144,1.27 9.144,0
  silkscreen extent 10.16,-0.65 13.97,1.92, body extent 5.25,-0.65 15.07,1.92, height 0.5
Jumper_filter#5 [mm] "Connector; Header; 2 Position"
  round 1.5 hole 0.9: 1(0,0) 2(2.54,0)
  rect 1x1.4 smd: 2(5.35,1.27) 2(7.35,1.27) 2(9.16,0) 2(12.97,1.27) 2(14.97,1.27) 3(11.16,0)
  Top Layer lines w0.152: 14.986,1.27 14.97,1.27 12.97,1.27 12.954,1.27 9.144,1.27 7.366,1.27 ; 5.334,1.27 5.35,1.27 7.35,1.27 7.366,1.27 ; 7.366,1.27 7.366,1.016 ; 7.366,1.27 7.366,1.016 ; 7.366,1.27 7.366,1.016 ; 7.366,1.27 7.366,1.016 ; 7.366,1.27 7.366,1.016 ; 7.366,1.27 7.366,1.016 ; 7.366,1.27 7.366,1.016 ; 7.366,1.27 7.366,1.016
  Top Layer lines w0.254: 16.51,0 16.095,0 11.43,0 ; 12.954,1.27 9.144,1.27 ; 7.366,1.27 9.144,1.27 ; 5.08,1.27 3.81,1.27 2.54,0 ; 9.144,1.27 9.144,0 ; 9.144,1.27 9.144,0 ; 9.144,1.27 9.144,0 ; 9.144,1.27 9.144,0 ; 9.144,1.27 9.144,0 ; 9.144,1.27 9.144,0 ; 9.144,1.27 9.144,0 ; 9.144,1.27 9.144,0
  silkscreen extent 10.16,-0.65 13.97,1.92, body extent 5.25,-0.65 15.07,1.92, height 0.5
Jumper_filter#6 [mm] "Connector; Header; 2 Position"
  round 1.5 hole 0.9: 1(0,0) 2(2.54,0)
  rect 1x1.4 smd: 2(5.35,1.27) 2(7.35,1.27) 2(9.16,0) 2(12.97,1.27) 2(14.97,1.27) 3(11.16,0)
  Top Layer lines w0.152: 5.334,1.27 5.35,1.27 7.35,1.27 7.366,1.27 ; 14.986,1.27 14.97,1.27 12.97,1.27 9.144,1.27 7.366,1.27 ; 7.366,1.27 7.366,1.016 ; 7.366,1.27 7.366,1.016 ; 7.366,1.27 7.366,1.016 ; 7.366,1.27 7.366,1.016 ; 7.366,1.27 7.366,1.016 ; 7.366,1.27 7.366,1.016 ; 7.366,1.27 7.366,1.016 ; 7.366,1.27 7.366,1.016
  Top Layer lines w0.254: 5.08,1.27 3.81,1.27 2.54,0 ; 7.366,1.27 9.144,1.27 ; 12.954,1.27 9.144,1.27 ; 11.43,0 16.51,0 ; 9.144,1.27 9.144,0 ; 9.144,1.27 9.144,0 ; 9.144,1.27 9.144,0 ; 9.144,1.27 9.144,0 ; 9.144,1.27 9.144,0 ; 9.144,1.27 9.144,0 ; 9.144,1.27 9.144,0 ; 9.144,1.27 9.144,0
  silkscreen extent 10.16,-0.65 13.97,1.92, body extent 5.25,-0.65 15.07,1.92, height 0.5
Jumper_filter#7 [mm] "Connector; Header; 2 Position"
  round 1.5 hole 0.9: 1(0,0) 2(2.54,0)
  rect 1x1.4 smd: 2(5.35,1.27) 2(7.35,1.27) 2(9.16,0) 2(12.97,1.27) 2(14.97,1.27) 3(11.16,0)
  Top Layer lines w0.152: 5.334,1.27 5.35,1.27 7.35,1.27 7.366,1.27 ; 14.986,1.27 14.97,1.27 14.884,1.27 14.86,1.27 12.97,1.27 12.954,1.27 9.144,1.27 7.366,1.27 ; 7.366,1.27 7.366,1.016 ; 7.366,1.27 7.366,1.016 ; 7.366,1.27 7.366,1.016 ; 7.366,1.27 7.366,1.016 ; 7.366,1.27 7.366,1.016 ; 7.366,1.27 7.366,1.016 ; 7.366,1.27 7.366,1.016 ; 7.366,1.27 7.366,1.016
  Top Layer lines w0.254: 5.08,1.27 3.81,1.27 2.54,0 ; 7.366,1.27 9.144,1.27 ; 12.954,1.27 9.144,1.27 ; 11.43,0 16.51,0 ; 9.144,1.27 9.144,0 ; 9.144,1.27 9.144,0 ; 9.144,1.27 9.144,0 ; 9.144,1.27 9.144,0 ; 9.144,1.27 9.144,0 ; 9.144,1.27 9.144,0 ; 9.144,1.27 9.144,0 ; 9.144,1.27 9.144,0
  silkscreen extent 10.16,-0.65 13.97,1.92, body extent 5.25,-0.65 15.07,1.92, height 0.5
Jumper_filter#8 [mm] "Connector; Header; 2 Position"
  round 1.5 hole 0.9: 1(0,0) 2(2.54,0)
  rect 1x1.4 smd: 2(5.35,1.27) 2(7.35,1.27) 2(9.16,0) 2(12.97,1.27) 2(14.97,1.27) 3(11.16,0)
  Top Layer lines w0.152: 5.334,1.27 5.35,1.27 7.35,1.27 7.366,1.27 ; 14.986,1.27 14.97,1.27 14.86,1.27 12.97,1.27 12.954,1.27 9.144,1.27 7.366,1.27 ; 7.366,1.27 7.366,1.016 ; 7.366,1.27 7.366,1.016 ; 7.366,1.27 7.366,1.016 ; 7.366,1.27 7.366,1.016 ; 7.366,1.27 7.366,1.016 ; 7.366,1.27 7.366,1.016 ; 7.366,1.27 7.366,1.016 ; 7.366,1.27 7.366,1.016
  Top Layer lines w0.254: 5.08,1.27 3.81,1.27 2.54,0 ; 7.366,1.27 9.144,1.27 ; 12.954,1.27 9.144,1.27 ; 11.43,0 16.51,0 ; 9.144,1.27 9.144,0 ; 9.144,1.27 9.144,0 ; 9.144,1.27 9.144,0 ; 9.144,1.27 9.144,0 ; 9.144,1.27 9.144,0 ; 9.144,1.27 9.144,0 ; 9.144,1.27 9.144,0 ; 9.144,1.27 9.144,0
  silkscreen extent 10.16,-0.65 13.97,1.92, body extent 5.25,-0.65 15.07,1.92, height 0.5
Jumper_filter#9 [mm] "Connector; Header; 2 Position"
  round 1.5 hole 0.9: 1(0,0) 2(2.54,0)
  rect 1x1.4 smd: 2(5.35,1.27) 2(7.35,1.27) 2(9.16,0) 2(12.97,1.27) 2(14.97,1.27) 3(11.16,0)
  Top Layer lines w0.152: 5.334,1.27 5.35,1.27 7.35,1.27 7.366,1.27 ; 14.986,1.27 14.97,1.27 14.641,1.27 12.97,1.27 12.954,1.27 9.144,1.27 7.366,1.27 ; 7.366,1.27 7.366,1.016 ; 7.366,1.27 7.366,1.016 ; 7.366,1.27 7.366,1.016 ; 7.366,1.27 7.366,1.016 ; 7.366,1.27 7.366,1.016 ; 7.366,1.27 7.366,1.016 ; 7.366,1.27 7.366,1.016 ; 7.366,1.27 7.366,1.016
  Top Layer lines w0.254: 5.08,1.27 3.81,1.27 2.54,0 ; 7.366,1.27 9.144,1.27 ; 12.954,1.27 9.144,1.27 ; 11.43,0 16.51,0 ; 9.144,1.27 9.144,0 ; 9.144,1.27 9.144,0 ; 9.144,1.27 9.144,0 ; 9.144,1.27 9.144,0 ; 9.144,1.27 9.144,0 ; 9.144,1.27 9.144,0 ; 9.144,1.27 9.144,0 ; 9.144,1.27 9.144,0
  silkscreen extent 10.16,-0.65 13.97,1.92, body extent 5.25,-0.65 15.07,1.92, height 0.5
Jumper_filter#10 [mm] "Connector; Header; 2 Position"
  round 1.5 hole 0.9: 1(0,0) 2(2.54,0)
  rect 1x1.4 smd: 2(5.35,1.27) 2(7.35,1.27) 2(9.16,0) 2(12.97,1.27) 2(14.97,1.27) 3(11.16,0)
  Top Layer lines w0.152: 14.986,1.27 14.97,1.27 12.97,1.27 12.954,1.27 9.144,1.27 8.89,1.27 7.366,1.27 ; 5.334,1.27 5.35,1.27 7.35,1.27 7.366,1.27 ; 7.366,1.27 7.366,1.016 ; 7.366,1.27 7.366,1.016 ; 7.366,1.27 7.366,1.016 ; 7.366,1.27 7.366,1.016 ; 7.366,1.27 7.366,1.016 ; 7.366,1.27 7.366,1.016 ; 7.366,1.27 7.366,1.016 ; 7.366,1.27 7.366,1.016
  Top Layer lines w0.254: 16.51,0 11.43,0 ; 12.954,1.27 9.144,1.27 ; 7.366,1.27 8.89,1.27 9.144,1.27 ; 5.08,1.27 3.81,1.27 2.54,0 ; 9.144,1.27 9.144,0.889 ; 9.144,0.889 9.144,0 ; 9.144,0.889 9.144,0 ; 9.144,0.889 9.144,0 ; 9.144,0.889 9.144,0 ; 9.144,0.889 9.144,0 ; 9.144,0.889 9.144,0 ; 9.144,0.889 9.144,0 ; 9.144,0.889 9.144,0
  silkscreen extent 10.16,-0.65 13.97,1.92, body extent 5.25,-0.65 15.07,1.92, height 0.5
Jumper_filter#11 [mm] "Connector; Header; 2 Position"
  round 1.5 hole 0.9: 1(0,0) 2(2.54,0)
  rect 1x1.4 smd: 2(5.35,1.27) 2(7.35,1.27) 2(9.16,0) 2(12.97,1.27) 2(14.97,1.27) 3(11.16,0)
  Top Layer lines w0.152: 14.986,1.27 14.97,1.27 12.97,1.27 12.954,1.27 9.144,1.27 7.366,1.27 ; 5.334,1.27 5.35,1.27 7.35,1.27 7.366,1.27 ; 7.366,1.27 7.366,1.016 ; 7.366,1.27 7.366,1.016 ; 7.366,1.27 7.366,1.016 ; 7.366,1.27 7.366,1.016 ; 7.366,1.27 7.366,1.016 ; 7.366,1.27 7.366,1.016 ; 7.366,1.27 7.366,1.016 ; 7.366,1.27 7.366,1.016
  Top Layer lines w0.254: 12.954,1.27 9.144,1.27 ; 7.366,1.27 9.144,1.27 ; 5.08,1.27 3.81,1.27 2.54,0 ; 16.51,0 16.32,0 ; 16.51,0 16.32,0 ; 16.51,0 16.32,0 ; 16.51,0 16.32,0 ; 16.51,0 16.32,0 ; 16.51,0 16.32,0 ; 16.51,0 16.32,0 ; 16.51,0 16.32,0 ; 16.32,0 11.43,0 ; 16.32,0 11.43,0 ; 16.32,0 11.43,0 ; 16.32,0 11.43,0 ; 16.32,0 11.43,0 ; 16.32,0 11.43,0 ; 16.32,0 11.43,0 ; 16.32,0 11.43,0 ; 9.144,1.27 9.144,0 ; 9.144,1.27 9.144,0 ; 9.144,1.27 9.144,0 ; 9.144,1.27 9.144,0 ; 9.144,1.27 9.144,0 ; 9.144,1.27 9.144,0 ; 9.144,1.27 9.144,0 ; 9.144,1.27 9.144,0
  silkscreen extent 10.16,-0.65 13.97,1.92, body extent 5.25,-0.65 15.07,1.92, height 0.5
Jumper_filter#12 [mm] "Connector; Header; 2 Position"
  round 1.5 hole 0.9: 1(0,0) 2(2.54,0)
  rect 1x1.4 smd: 2(5.35,1.27) 2(7.35,1.27) 2(9.16,0) 2(12.97,1.27) 2(14.97,1.27) 3(11.16,0)
  Top Layer lines w0.152: 14.986,1.27 14.97,1.27 12.97,1.27 12.954,1.27 9.144,1.27 7.366,1.27 ; 7.366,1.016 7.366,1.27 ; 5.334,1.27 5.35,1.27 7.35,1.27 7.366,1.27
  Top Layer lines w0.254: 16.51,0 11.43,0 ; 12.954,1.27 9.144,1.27 ; 9.144,0 9.144,1.27 ; 7.366,1.27 9.144,1.27 ; 5.08,1.27 3.81,1.27 2.54,0
  silkscreen extent 10.16,-0.65 13.97,1.92, body extent 5.25,-0.65 15.07,1.92, height 0.5
Jumper_filter#13 [mm] "Connector; Header; 2 Position"
  round 1.5 hole 0.9: 1(0,0) 2(2.54,0)
  rect 1x1.4 smd: 2(5.35,1.27) 2(7.35,1.27) 2(9.16,0) 2(12.97,1.27) 2(14.97,1.27) 3(11.16,0)
  Top Layer lines w0.152: 7.366,1.016 7.366,1.27 ; 14.986,1.27 14.97,1.27 14.732,1.27 12.97,1.27 12.954,1.27 9.144,1.27 7.366,1.27 ; 5.334,1.27 5.35,1.27 7.35,1.27 7.366,1.27
  Top Layer lines w0.254: 16.51,0 11.43,0 ; 9.144,0 9.144,1.27 ; 2.54,0 3.81,1.27 5.08,1.27 ; 12.954,1.27 9.144,1.27 ; 7.366,1.27 9.144,1.27
  silkscreen extent 10.16,-0.65 13.97,1.92, body extent 5.25,-0.65 15.07,1.92, height 0.5
Jumper_filter#14 [mm] "Connector; Header; 2 Position"
  round 1.5 hole 0.9: 1(0,0) 2(2.54,0)
  rect 1x1.4 smd: 2(5.35,1.27) 2(7.35,1.27) 2(9.16,0) 2(12.97,1.27) 2(14.97,1.27) 3(11.16,0)
  Top Layer lines w0.152: 5.334,1.27 5.35,1.27 7.35,1.27 7.366,1.27 ; 14.986,1.27 14.97,1.27 12.97,1.27 12.954,1.27 10.43,1.27 9.144,1.27 7.366,1.27 ; 7.366,1.27 7.366,1.016 ; 7.366,1.27 7.366,1.016 ; 7.366,1.27 7.366,1.016 ; 7.366,1.27 7.366,1.016 ; 7.366,1.27 7.366,1.016 ; 7.366,1.27 7.366,1.016 ; 7.366,1.27 7.366,1.016 ; 7.366,1.27 7.366,1.016
  Top Layer lines w0.254: 5.08,1.27 3.81,1.27 2.54,0 ; 7.366,1.27 9.144,1.27 ; 12.954,1.27 10.43,1.27 9.144,1.27 ; 11.43,0 16.51,0 ; 9.144,1.27 9.144,0 ; 9.144,1.27 9.144,0 ; 9.144,1.27 9.144,0 ; 9.144,1.27 9.144,0 ; 9.144,1.27 9.144,0 ; 9.144,1.27 9.144,0 ; 9.144,1.27 9.144,0 ; 9.144,1.27 9.144,0
  silkscreen extent 10.16,-0.65 13.97,1.92, body extent 5.25,-0.65 15.07,1.92, height 0.5
"Layer Plot" [mm]
  Top Layer lines w0.635: -12.7,-5.08 12.7,-5.08 12.7,5.08 -12.7,5.08 -12.7,-5.08
  Bottom Layer lines w0.635: -12.7,-5.08 12.7,-5.08 12.7,5.08 -12.7,5.08 -12.7,-5.08
  Internal Plane 2 pour cut-out: 1.016,4.445 1.016,4.75 -12.37,4.75 -12.37,-4.75 12.37,-4.75 12.37,4.75 1.016,4.75 1.016,4.445 -0.635,2.794 -0.635,2.286 -0.254,1.905 0.254,1.905 1.524,3.175 3.556,3.175 4.445,2.286 4.445,1.524 4.42,1.524 3.531,0.635 2.286,0.635 1.905,0.254 1.905,-0.254 2.286,-0.635 3.556,-0.635 4.445,-1.524 4.445,-2.286 3.556,-3.175 1.524,-3.175 0.254,-1.905 -0.254,-1.905 -0.635,-2.286 -0.635,-2.794 1.016,-4.445 4.064,-4.445 5.715,-2.794 5.715,-1.016 4.699,0 5.715,1.016 5.715,2.794 4.064,4.445
  Internal Plane 2 lines w0.635: -12.7,-5.08 12.7,-5.08 12.7,5.08 -12.7,5.08 -12.7,-5.08
  Internal Plane 1 pour cut-out: -5.791,4.42 -5.791,4.75 -12.37,4.75 -12.37,-4.75 12.37,-4.75 12.37,4.75 -5.791,4.75 -5.791,4.42 -7.417,2.794 -7.417,2.235 -7.061,1.88 -6.528,1.88 -5.258,3.15 -3.251,3.15 -2.362,2.261 -2.362,1.499 -7.442,-3.581 -7.442,-4.064 -7.036,-4.47 -1.499,-4.47 -1.092,-4.064 -1.092,-3.658 -1.549,-3.2 -5.283,-3.2 -5.283,-3.175 -1.092,1.016 -1.092,2.692 -2.819,4.42
  Internal Plane 1 lines w0.635: -12.7,-5.08 12.7,-5.08 12.7,5.08 -12.7,5.08 -12.7,-5.08
LDO [mm] "Low-dropout Regulator"
  round 1.5 hole 0.9: EN1(31.75,40.132) EN2(31.75,28.702) EN3(31.75,17.272) EN4(31.75,5.842) GND(31.75,31.242) GND(31.75,42.672) GND(31.75,8.382) GND(31.75,19.812) VIN(2.54,43.942) VOUT1(31.75,45.212) VOUT2(31.75,33.782) VOUT3(31.75,22.352) VOUT4(31.75,10.922)
  rect 1.5x1.5 hole 0.9: GND(2.54,41.402) RST1(31.75,37.592) RST2(31.75,26.162) RST3(31.75,14.732) RST4(31.75,3.302)
  round 1 hole 0.3: ""(1.683,3.81) ""(1.951,4.81) ""(1.951,2.81) ""(2.683,5.542) ""(2.683,2.078) ""(3.683,5.81) ""(3.683,1.81) ""(4.683,5.542) ""(4.683,2.078) ""(5.415,4.81) ""(5.415,2.81) ""(5.683,3.81)
  round 5 hole 3: ""(3.683,3.81)
  silkscreen extent 0,0 34.9,46.9
LOGO [mm]
  silkscreen extent 0,-1.4 65,31
LVSwitcher [mm] "Low-Voltage Switching Regulator"
  round 1.5 hole 0.9: EN(46,19.615) GND(3.975,29.775) GND(3.975,32.315) GND(3.975,27.235) GND(46,32.315) GND(46,34.855) GND(46,37.395) SYNC(46,17.075) Vin(3.975,19.615) Vin(3.975,22.155) Vin(3.975,24.695) Vin(3.975,17.075) Vout(46,22.155) Vout(46,24.695) Vout(46,27.235) Vout(46,29.775)
  rect 1.5x1.5 hole 0.9: GND(3.975,34.855) PG(46,14.535)
  round 1 hole 0.3: ""(2,46) ""(2,4) ""(2.268,45) ""(2.268,47) ""(2.268,3) ""(2.268,5) ""(3,44.268) ""(3,47.732) ""(3,5.732) ""(3,2.268) ""(4,44) ""(4,48) ""(4,6) ""(4,2) ""(5,44.268) ""(5,47.732) ""(5,2.268) ""(5,5.732) ""(5.732,45) ""(5.732,47) ""(5.732,3) ""(5.732,5) ""(6,46) ""(6,4) ""(44,4) ""(44,46) ""(44.268,3) ""(44.268,5) ""(44.268,45) ""(44.268,47) ""(45,47.732) ""(45,2.268) ""(45,5.732) ""(45,44.268) ""(46,48) ""(46,2) ""(46,6) ""(46,44) ""(47,47.732) ""(47,2.268) ""(47,5.732) ""(47,44.268) ""(47.732,3) ""(47.732,5) ""(47.732,45) ""(47.732,47) ""(48,4) ""(48,46)
  round 5 hole 3: ""(4,46) ""(4,4) ""(46,4) ""(46,46)
  silkscreen extent 0,0 50,50
"R/A RCA" [mm] "LUMBERG - WBTOR 1"
  round 2 hole 1.5: 0(-3.75,0) 0(3.75,0)
  round 2.2 hole 1.7: 0(0,-6.5)
  oval 2x3.4 hole 1 slot 2.4 at 90 deg: 1(5.3,-8)
  oval 3.4x2.6 hole 1.6 slot 2.4 at 0 deg: 2(0,0)
  silkscreen extent -6,-10 6,13
"Registration Check" [mm]
  Top Layer lines w0.152: -2.667,0 0,0 ; 0,-2.667 0,0 ; 0,2.667 0,0 ; 2.667,0 0,0
  Bottom Layer lines w0.152: -2.667,0 0,0 ; 0,-2.667 0,0 ; 0,2.667 0,0 ; 2.667,0 0,0
  Internal Plane 2 pour cut-out: 0,2.743 0,3.2 -3.2,3.2 -3.2,-3.2 3.2,-3.2 3.2,3.2 0,3.2 0,2.743 -0.076,2.667 -0.076,0.076 -2.667,0.076 -2.743,0 -2.692,-0.051 -2.692,-0.076 -0.076,-0.076 -0.076,-2.667 0,-2.743 0.076,-2.667 0.076,-0.076 2.667,-0.076 2.743,0 2.667,0.076 0.076,0.076 0.076,2.667
  Internal Plane 1 pour cut-out: 0,2.743 0,3.2 -3.2,3.2 -3.2,-3.2 3.2,-3.2 3.2,3.2 0,3.2 0,2.743 -0.076,2.667 -0.076,0.076 -2.667,0.076 -2.743,0 -2.692,-0.051 -2.692,-0.076 -0.076,-0.076 -0.076,-2.667 0,-2.743 0.076,-2.667 0.076,-0.076 2.667,-0.076 2.743,0 2.667,0.076 0.076,0.076 0.076,2.667
SCREW2 [mm]
  round 2.54 hole 1.5: 1(-2.54,0) 2(2.54,0)
  silkscreen extent -5.59,-5.08 5.59,5.08
SCREW3 [mm]
  round 2.54 hole 1.5: 1(-5.08,0) 2(0,0) 3(5.08,0)
  silkscreen extent -8.13,-5.08 8.13,5.08
SOMC1603 [mm]
  oval 2.5x0.7 smd: 1(1.741,9.906) 2(1.741,8.636) 3(1.741,7.366) 4(1.741,6.096) 5(1.741,4.826) 6(1.741,3.556) 7(1.741,2.286) 8(1.741,1.016) 9(8.316,1.016) 10(8.316,2.286) 11(8.316,3.556) 12(8.316,4.826) 13(8.316,6.096) 14(8.316,7.366) 15(8.316,8.636) 16(8.316,9.906)
  silkscreen extent 1.62,0.46 6.68,10.93, body extent 2.19,0.45 7.88,10.46, height 1.75
TO229P990X238-3N [mm] "D-PAK, 3-Pads, Body 6.2x6.7mm (max), IPC Medium Density"
  rect 3.05x1 smd: 1(-4.05,-2.29) 1(-4.05,2.29)
  rect 6.5x5.55 smd: 2(2.4,0)
  silkscreen extent -4.17,-3.35 -1.25,3.46, body extent -2.1,-3.37 4.12,3.37, height 2.38
TRX_REGULATOR [mm]
  round 1.5 hole 0.9: 1(27.018,2.962) 1(29.558,2.962) 1(32.098,2.962) 2(3.65,32.045) 2(34.638,2.962) 2(37.178,2.962) 2(42.791,35.27) 3(19.474,29.149) 4(16.934,29.149) 5(37.711,35.27) 5(40.251,35.27) 6(6.19,32.045) 6(8.73,32.045) 7(14.394,29.149)
  rect 1.5x1.5 hole 0.9: 2(1.11,32.045) 2(22.014,29.149) 2(39.718,2.962) 2(45.331,35.27)
  round 1 hole 0.3: ""(1.291,43.161) ""(1.291,3.161) ""(1.559,44.161) ""(1.559,42.161) ""(1.559,4.161) ""(1.559,2.161) ""(2.291,44.893) ""(2.291,41.429) ""(2.291,4.893) ""(2.291,1.429) ""(3.291,45.161) ""(3.291,41.161) ""(3.291,5.161) ""(3.291,1.161) ""(4.291,44.893) ""(4.291,41.429) ""(4.291,4.893) ""(4.291,1.429) ""(5.023,42.161) ""(5.023,44.161) ""(5.023,4.161) ""(5.023,2.161) ""(5.291,43.161) ""(5.291,3.161) ""(41.291,43.161) ""(41.559,42.161) ""(41.559,44.161) ""(42.291,41.429) ""(42.291,44.893) ""(43.291,41.161) ""(43.291,45.161) ""(44.291,41.429) ""(44.291,44.893) ""(45.023,42.161) ""(45.023,44.161) ""(45.291,43.161)
  round 5 hole 3: ""(3.291,43.161) ""(3.291,3.161) ""(43.291,43.161)
  round 4 hole 3.5: ""(43.291,3.161)
  silkscreen extent -0.41,-0.54 46.98,46.86
TSSOP50P310X90-8N [mm] "TSSOP, 8-Leads, Body 2.1x2.4mm (max), Pitch 0.50mm, IPC Medium Density"
  oval 1.25x0.3 smd mask+0.102: 1(-1.325,0.75) 2(-1.325,0.25)
  oval 1.25x0.3 smd: 3(-1.325,-0.25) 4(-1.325,-0.75) 5(1.325,-0.75) 6(1.325,-0.25) 7(1.325,0.25) 8(1.325,0.75)
  silkscreen extent -1.45,-1.05 0.3,1.57, body extent -1.2,-1.05 1.2,1.05, height 0.9

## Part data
C1: library part "0805 MLCC - X7R, 10%", "0805 MLCC - X7R, 10%"
C2 C3 C4 C5 C6 C7 C8 C9 C10 C11 C12 C13: library part Cap, "Capacitor"
CSC1: library part CSC
D1: library part "D Schottky", "Schottky Diode"
J1 J2 J3 J6 J7 J8 J9 J25 J26 J27 J28 J29 J30 J31 J32 J33 J34: library part "Header 3", "Header, 3-Pin"
J4 J5: library part Socket, "Socket"
J10 J11 J12: library part "Header 4", "Header, 4-Pin"
J13 J14 J17 J18 J23 J24: library part "Header 2", "Header, 2-Pin"
J15 J16: library part "D Connector 9", "Receptacle Assembly, 9 Position, Right Angle"
J19 J20 J21 J22: library part RCA, "RCA Phono Jack, Right Angle, Thru-Hole, Snap-In"
J35 J36: library part "Header 8", "Header, 8-Pin"
LDO1 LDO2: library part LDO
LED1 LED2 LED3 LED4 LED5 LED18 LED37 LED56 LED57 LED58 LED59 LED60 LED61 LED62 LED81 LED100: library part LED0, "Typical INFRARED GaAs LED"
LED6 LED7 LED8 LED9 LED10 LED11 LED12 LED13 LED14 LED15 LED16 LED17 LED19 LED20 LED21 LED22 LED23 LED24 LED25 LED26 LED27 LED28 LED29 LED30 LED31 LED32 LED33 LED34 LED35 LED36 LED38 LED39 LED40 LED41 LED42 LED43 LED44 LED45 LED46 LED47 LED48 LED49 LED50 LED51 LED52 LED53 LED54 LED55 LED63 LED64 LED65 LED66 LED67 LED68 LED69 LED70 LED71 LED72 LED73 LED74 LED75 LED76 LED77 LED78 LED79 LED80 LED82 LED83 LED84 LED85 LED86 LED87 LED88 LED89 LED90 LED91 LED92 LED93 LED94 LED95 LED96 LED97 LED98 LED99 LED101 LED102 LED103 LED104 LED105 LED106 LED107 LED108 LED109 LED111 LED112: library part "BIDIRECTIONAL LED"
LOGO: library part LOGO
R1 R2 R3 R4 R5 R6 R7 R8 R9 R10 R11: library part "1206 Thick Film Resistor 1%", "1206 Thick Film Resistor 1%"
R12 R13 R14 R15 R16 R17 R18 R19 R20 R21 R22 R23 R24 R25 R26 R27: "Resistor"
SW1 SW2: library part LVSWITCHER
U2 U3 U4 U5 U6 U7 U14 U15 U16 U17 U18 U19: "Octal Bus Buffer"

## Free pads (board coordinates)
  round 1.524 hole 0.8: 0(25.019,4.953) 0(78.359,4.801) 0(113.36,11.506) 0(166.765,11.504) 0(220.359,11.504) 0(273.953,11.504) 1(25.019,2.794) 1(78.359,2.413) 1(115.926,11.506) 1(168.645,11.504) 1(222.239,11.504) 1(275.833,11.504)

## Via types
v1: diameter 1.016, hole 0.508, Top Layer to Bottom Layer, 541 vias
v2: diameter 0.6, hole 0.3, Top Layer to Bottom Layer, 214 vias
v3: diameter 1.27, hole 0.711, Top Layer to Bottom Layer, 147 vias
v4: diameter 0.8, hole 0.5, Top Layer to Bottom Layer, 31 vias
v5: diameter 0.5, hole 0.3, Top Layer to Bottom Layer, tented bottom, 5 vias
v6: diameter 1.27, hole 0.635, Top Layer to Bottom Layer, tented both sides, 1 vias

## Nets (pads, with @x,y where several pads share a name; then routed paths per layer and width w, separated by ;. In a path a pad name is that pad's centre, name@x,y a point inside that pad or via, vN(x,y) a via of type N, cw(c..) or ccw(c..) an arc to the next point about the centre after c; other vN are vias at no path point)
3V3_AUX: F5.1 P520.1 R19.2 | length 288.3
  Top Layer w0.508: v3(197.279,164.561) 226.056,135.785 v3(262.403,135.785) ; v1(350.803,59.785) 350.803,40.665 361.703,29.765 R19.2@361.803,29.765
  Top Layer w0.762: v1(19,164.257) v1(19,165.96) F5.1@19,168.25 F5.1@19,168.436
  Bottom Layer w0.508: P520.1@165.688,167.75 165.921,167.75 167.103,166.568 186.387,166.568 187.181,165.774 196.066,165.774 v3(197.279,164.561) ; v3(262.403,135.785) 265.003,135.785 269.703,131.085 269.703,123.212 286.23,106.685 286.23,87.658 300.903,72.985 344.103,72.985 350.903,66.185 v1@350.903,59.785
3V3_AUX_E\N\: J32.2 P521.1 | length 5.1
  Top Layer w0.508: J32.2@160.608,172.83 P521.1@165.688,172.83
3V3_BBONE: F4.1 P3.1 P4.1 R1.1 R2.1 | length 608.9
  Top Layer w0.508: v3(377.266,275.311) 377.47,275.514 377.47,286.72 v3(377.5,286.75)
  Top Layer w0.762: v3(4.343,202.54) 4.346,202.537 F4.1@6.286,202.537 6.286,199.962 10.859,199.962 10.859,202.661 11.176,202.978 R1.1@13.97,202.978
  Bottom Layer w0.508: v3(4.343,202.54) 4.592,202.54 4.595,202.537 4.595,214.628 1.448,217.775 1.448,319.1 25.61,343.263 286.494,343.263 288.679,345.448 375.658,345.448 377.5,343.606 377.5,286.11 ; v3(377.266,275.311) 382.524,270.053 383.796,270.053 384.964,268.884 389.039,268.884 P4.1@390.478,267.445 P3.1@393.018,267.445
3V3_COMMS: P127.1 P129.1 P177.1 P526.1 R17.2 | length 255.4
  Top Layer w0.508: P127.1@213.21,206.992 213.496,206.992 226.103,194.385 226.103,181.785 v3(261.603,146.285) ; v3(299.303,109.085) 299.309,109.091 322.997,109.091 354.417,77.671 354.417,41.071 360.803,34.685 361.563,34.685 R17.2@361.803,34.925
  Bottom Layer w0.508: v3(261.603,146.285) 261.603,145.958 276.888,130.673 276.888,119.9 287.703,109.085 v3(299.303,109.085)
3V3_CSC: F3.1 P189.1 P203.1 P223.1 P249.1 P290.1 P293.1 P523.1 R3.1 R4.1 R7.1 R8.1 R18.2 | length 353.3
  Top Layer w0.254: v3(27.051,175.514) 27.051,167.321 30.992,163.38 32.519,163.38 P290.1@33.979,161.92 ; R8.1@45.069,161.925 R7.1@45.069,164.592 45.069,175.625 v3(45.085,175.641)
  Top Layer w0.508: v3(198.303,165.585) 226.655,137.233 v3(262.403,137.233) ; v3(352.003,62.185) 352.003,41.725 361.703,32.025 R18.2@361.803,32.025
  Top Layer w0.762: F3.1@5.295,230.528 5.295,228.435 6.299,227.432 16.632,227.432 v3(16.8,227.6) ; 10.312,227.533 R4.1@10.312,230.877 ; 13.183,227.457 R3.1@13.183,230.877
  Bottom Layer w0.508: P189.1@15.443,294.956 17,296.513 17,300.3 18.3,301.6 18.3,304.08 P293.1@20.654,306.434 ; P523.1@165.688,177.91 165.688,177.7 166.803,176.585 187.773,176.585 188.853,175.505 188.853,175.035 v3(198.303,165.585) ; v3(262.403,137.233) 265.855,137.233 270.976,132.112 270.976,124.112 287.503,107.585 287.503,88.185 301.403,74.285 344.603,74.285 352.003,66.885 v3(352.003,62.185)
3V3_PWR: P198.1 P393.1 P394.1 P436.1 P442.1 P517.1 R5.1 R6.1 R16.2 | length 556.8
  Top Layer w0.508: P198.1@15.443,267.016 17.145,265.313 17.145,255.145 v3(15.5,253.5) ; v3(287,23) R5.1@287,27.5 R6.1@287,30 ; P436.1@322.287,17.64 323.532,18.885 333.903,18.885 v3(344.703,29.685) ; v3(359.903,37.185) 361.723,37.185 R16.2@361.803,37.105
  Bottom Layer w0.508: v3(15.5,253.5) 15.5,248.775 11.938,245.213 11.938,207.645 21.971,197.612 21.971,176.279 25.48,172.77 v1(25.48,157.55) v1(25.48,155.264) 25.48,140.278 ; P394.1@20.451,80.272 19.13,81.593 19.13,83.636 25.48,89.986 25.48,140.278 ; P393.1@20.451,134.12 20.451,135.249 25.48,140.278 ; v3(344.703,29.685) 352.203,37.185 v3(359.903,37.185)
  Bottom Layer w0.762: P517.1@165.688,157.59 184.27,139.008 232.744,139.008 241.767,129.985 241.767,128.321 241.888,128.2 241.888,36.392 253.572,24.708 285.324,24.708 294.468,15.564 ; P442.1@270.971,17.874 273.281,15.564 294.468,15.564 ; P436.1@322.287,17.64 320.211,15.564 294.468,15.564
3V3_UNREG: C2.2 C3.2 C4.2 C5.2 C6.2 C7.2 C8.2 C9.2 C10.2 C11.2 C12.2 C13.2 J27.1 J28.1 J31.1 J32.1 LED6.3 LED7.3 LED8.3 LED9.3 LED10.3 LED11.3 LED12.3 LED13.3 LED14.3 LED15.3 LED16.3 LED17.3 LED19.3 LED20.3 LED21.3 LED22.3 LED23.3 LED24.3 LED25.3 LED26.3 LED27.3 LED28.3 LED29.3 LED30.3 LED31.3 LED32.3 LED33.3 LED34.3 LED35.3 LED36.3 LED38.3 LED39.3 LED40.3 LED41.3 LED42.3 LED43.3 LED44.3 LED45.3 LED46.3 LED47.3 LED48.3 LED49.3 LED50.3 LED51.3 LED52.3 LED53.3 LED54.3 LED55.3 LED63.3 LED64.3 LED65.3 LED66.3 LED67.3 LED68.3 LED69.3 LED70.3 LED71.3 LED72.3 LED73.3 LED74.3 LED75.3 LED76.3 LED77.3 LED78.3 LED79.3 LED80.3 LED82.3 LED83.3 LED84.3 LED85.3 LED86.3 LED87.3 LED88.3 LED89.3 LED90.3 LED91.3 LED92.3 LED93.3 LED94.3 LED95.3 LED96.3 LED97.3 LED98.3 LED99.3 LED101.3 LED102.3 LED103.3 LED104.3 LED105.3 LED106.3 LED107.3 LED108.3 LED109.3 LED111.3 LED112.3 P481.1 P482.1 P483.1 P484.1 P505.1 R14.2 U2.20 U3.20 U4.20 U5.20 U6.20 U7.20 U14.20 U15.20 U16.20 U17.20 U18.20 U19.20 | length 1273.5
  Top Layer w0.508: LED51.3@65.75,143.75 LED45.3@68.25,143.75 LED39.3@70.75,143.75 LED32.3@73.25,143.75 LED26.3@75.75,143.75 LED20.3@78.25,143.75 LED13.3@80.75,143.75 LED7.3@83.25,143.75 84.5,143.75 ; U3.20@81.43,162 81.43,158.57 C3.2@81.5,158.5 81.561,158.5 84.5,155.561 ; U2.20@101.505,162.125 C2.2@101.505,158.875 101.375,158.875 98.061,155.561 84.5,155.561 ; C5.2@122.003,158.92 U5.20@122.003,162.1 ; C5.2@122.073,158.85 130.202,158.85 133.858,155.194 133.858,143.75 ; LED89.3@123.25,143.75 LED95.3@120.75,143.75 LED22.3@118.25,143.75 LED28.3@115.75,143.75 LED34.3@113.25,143.75 LED41.3@110.75,143.75 LED47.3@108.25,143.75 LED53.3@105.75,143.75 LED6.3@103.25,143.75 LED12.3@100.75,143.75 LED19.3@98.25,143.75 LED25.3@95.75,143.75 LED31.3@93.25,143.75 LED38.3@90.75,143.75 LED44.3@88.25,143.75 LED50.3@85.75,143.75 84.5,143.75 ; U18.20@144.25,323.25 144.18,323.32 C12.2@144.18,326.5 143.895,326.5 141.225,329.17 141.225,342.225 142.475,342.225 LED67.3@142.5,342.25 LED73.3@145,342.25 LED79.3@147.5,342.25 LED86.3@150,342.25 LED92.3@152.5,342.25 LED98.3@155,342.25 LED105.3@157.5,342.25 LED111.3@160,342.25 161.225,342.25 ; 156.972,307.594 156.972,311.912 ; U19.20@165,323 164.93,323.07 C13.2@164.93,326.25 164.645,326.25 161.225,329.67 161.225,342.25 ; LED54.3@171.25,272.75 LED48.3@171.25,270.25 LED42.3@171.25,267.75 LED35.3@171.25,265.25 LED29.3@171.25,262.75 LED23.3@171.25,260.25 LED16.3@171.25,257.75 LED10.3@171.25,255.25 171.25,254 ; LED112.3@180,342.25 LED106.3@177.5,342.25 LED99.3@175,342.25 LED93.3@172.5,342.25 LED87.3@170,342.25 LED80.3@167.5,342.25 LED74.3@165,342.25 LED68.3@162.5,342.25 161.225,342.25 ; U6.20@190.25,256.32 190.18,256.25 C6.2@187,256.25 187,256.189 184.811,254 171.25,254 ; U7.20@197.75,231.32 197.68,231.25 C7.2@194.5,231.25 194.5,231.189 188.561,225.25 180.75,225.25 178.5,227.5 173.939,227.5 171.25,230.189 LED11.3@171.25,230.25 LED30.3@171.25,237.75 LED43.3@171.25,242.75 LED63.3@171.25,250.25 171.25,254 ; U4.20@242.25,246.43 242.32,246.5 C4.2@245.5,246.5 246.368,245.632 246.368,245.301 250.643,241.026 250.643,234.676 251.25,234.069 251.25,217 ; LED15.3@247.25,217 LED15.3@247.5,217 251.25,217 ; LED8.3@270,217 LED14.3@267.5,217 LED21.3@265,217 LED27.3@262.5,217 LED33.3@260,217 LED40.3@257.5,217 LED46.3@255,217 LED52.3@252.5,217 251.25,217 ; LED65.3@292.5,196.5 LED71.3@292.5,199 LED77.3@292.5,201.5 LED84.3@292.5,204 LED90.3@292.5,206.5 LED96.3@292.5,209 LED103.3@292.5,211.5 LED109.3@292.5,214 292.5,215.25 ; LED104.3@292.5,231.5 LED97.3@292.5,229 LED91.3@292.5,226.5 LED85.3@292.5,224 LED78.3@292.5,221.5 LED72.3@292.5,219 LED66.3@292.5,216.5 292.5,215.25 ; U16.20@313.421,198.07 313.351,198 C10.2@310.171,198 309.303,198.868 309.303,199.182 307.171,201.314 307.171,215.25 ; U17.20@313.421,218.07 313.351,218 C11.2@310.171,218 310.171,217.939 307.482,215.25 307.171,215.25 ; v3(359.403,47.485) 359.423,47.465 361.803,47.465 ; R14.2@361.803,42.265 361.803,47.465 ; LED108.3@364.808,44.865 LED102.3@364.808,47.465 363.312,47.465 363.092,47.245 362.314,47.245 362.094,47.465 361.803,47.465 ; U15.20@376.25,299.68 C9.2@379.009,299.68 ; U14.20@376.43,313 C8.2@379.25,313 379.25,312.939 380.932,311.258 380.932,301.426 379.25,299.744 C9.2@379.25,299.5 379.25,299.439 380.768,297.922 387.299,297.922 387.914,297.307 395.75,297.307 ; 395.75,274.683 LED83.3@395.75,288.5 LED76.3@395.75,291 LED70.3@395.75,293.5 LED64.3@395.75,296 395.75,297.307 ; LED75.3@395.75,311 LED82.3@395.75,308.5 LED88.3@395.75,306 LED94.3@395.75,303.5 LED101.3@395.75,301 LED107.3@395.75,298.5 395.75,297.307 ; 84.5,143.75 84.5,155.561 ; 292.5,215.25 307.171,215.25
  Top Layer w1.27: LED89.3@123.25,143.75 133.858,143.75 194.296,143.75 v3(203.454,152.908) v3(203.454,155.829) ; 156.972,307.594 154.94,305.562 154.94,279.4 161.59,272.75 LED54.3@171.25,272.75 ; 156.972,311.912 163.068,318.008 179.197,318.008 183.007,321.818 183.007,340.995 181.752,342.25 LED112.3@180,342.25 ; LED11.3@171.25,230.25 168.402,227.402 168.402,216.281 177.165,207.518 190.754,207.518 v3(203.073,195.199) v3(203.073,192.786) ; v3(242.57,200.152) v3(244.856,200.152) v3(247.523,200.152) 247.5,200.175 LED15.3@247.5,217 ; v3(269.367,189.103) v3(271.907,189.103) v3(274.447,189.103) 308.356,189.103 310.007,190.754 310.007,192.151 312.928,195.072 314.833,195.072 317.627,197.866 317.627,229.108 321.437,232.918 362.712,232.918 364.744,234.95 371.298,234.95 371.326,234.922 388.465,234.922 402.971,249.428 402.971,267.462 395.75,274.683 ; v3(269.398,196.5) v3(271.938,196.5) v3(274.447,196.5) LED65.3@292.5,196.5
  Bottom Layer w0.254: J27.1@160.608,159.836 162.56,161.788 162.56,170.18 ; J32.1@160.608,170.25 162.49,170.25 162.56,170.18 ; J31.1@160.608,180.41 162.503,180.41 162.56,180.467 ; J28.1@160.608,190.57 162.49,190.57 162.56,190.5 ; v3(175.133,200.279) 166.116,200.279 162.56,196.723 162.56,190.5 ; 162.56,170.18 162.56,180.467 ; 162.56,180.467 162.56,190.5
  Bottom Layer w0.508: v1(260.403,157.485) 260.403,132.276 262.063,130.616 262.063,126.925 271.603,117.385 271.603,79.385 284.103,66.885 337.103,66.885 347.303,56.685 355.703,56.685 359.403,52.985 v3(359.403,47.485)
3V3_UNREG_PG: P485.1 U15.8 | length 178.6
  Top Layer w0.152: P485.1@262.208,194.42 262.208,201.879 273.86,213.531 273.86,217.433 274.8,218.372 274.8,228.183 274.595,228.388 274.595,264.468 301.177,291.05 366.49,291.05 U15.8@366.75,290.79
